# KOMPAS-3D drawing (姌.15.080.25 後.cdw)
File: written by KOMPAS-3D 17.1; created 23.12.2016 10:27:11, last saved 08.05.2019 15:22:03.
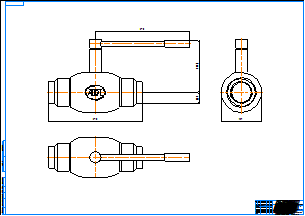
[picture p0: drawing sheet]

Sheet 1: A0, landscape

Title block, sheet 1: name: КШ.15.080.25 сс; material: Внимание! Данный продукт является объектом авторского права ООО «Торговый Дом АДЛ». / Запрещается изменение, копирование, распространение / (в том числе путем копирования на другие сайты и ресурсы в Интернете) / или любое иное использование информации и объектов без предварительного / согласия правообладателя (ООО «Торговый Дом АДЛ»).; sheets: 1; organisation: ООО "Торговый дом АДЛ"; sheet format: A0; stored path: C:\Users\tra\Desktop\2д чертежи\Шаровые краны БИВАЛ\КШ_Бивал_серия_14_15\KOMPAS_2D\КШ.15.080.25 сс.cdw

Views: Вид 1, Проекционный вид 2, Проекционный вид 3
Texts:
  Klimkovich
  ADL
Dimensions and other numbers on the sheet: 370; 205,1; 44,5; 159; 1:1; 1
